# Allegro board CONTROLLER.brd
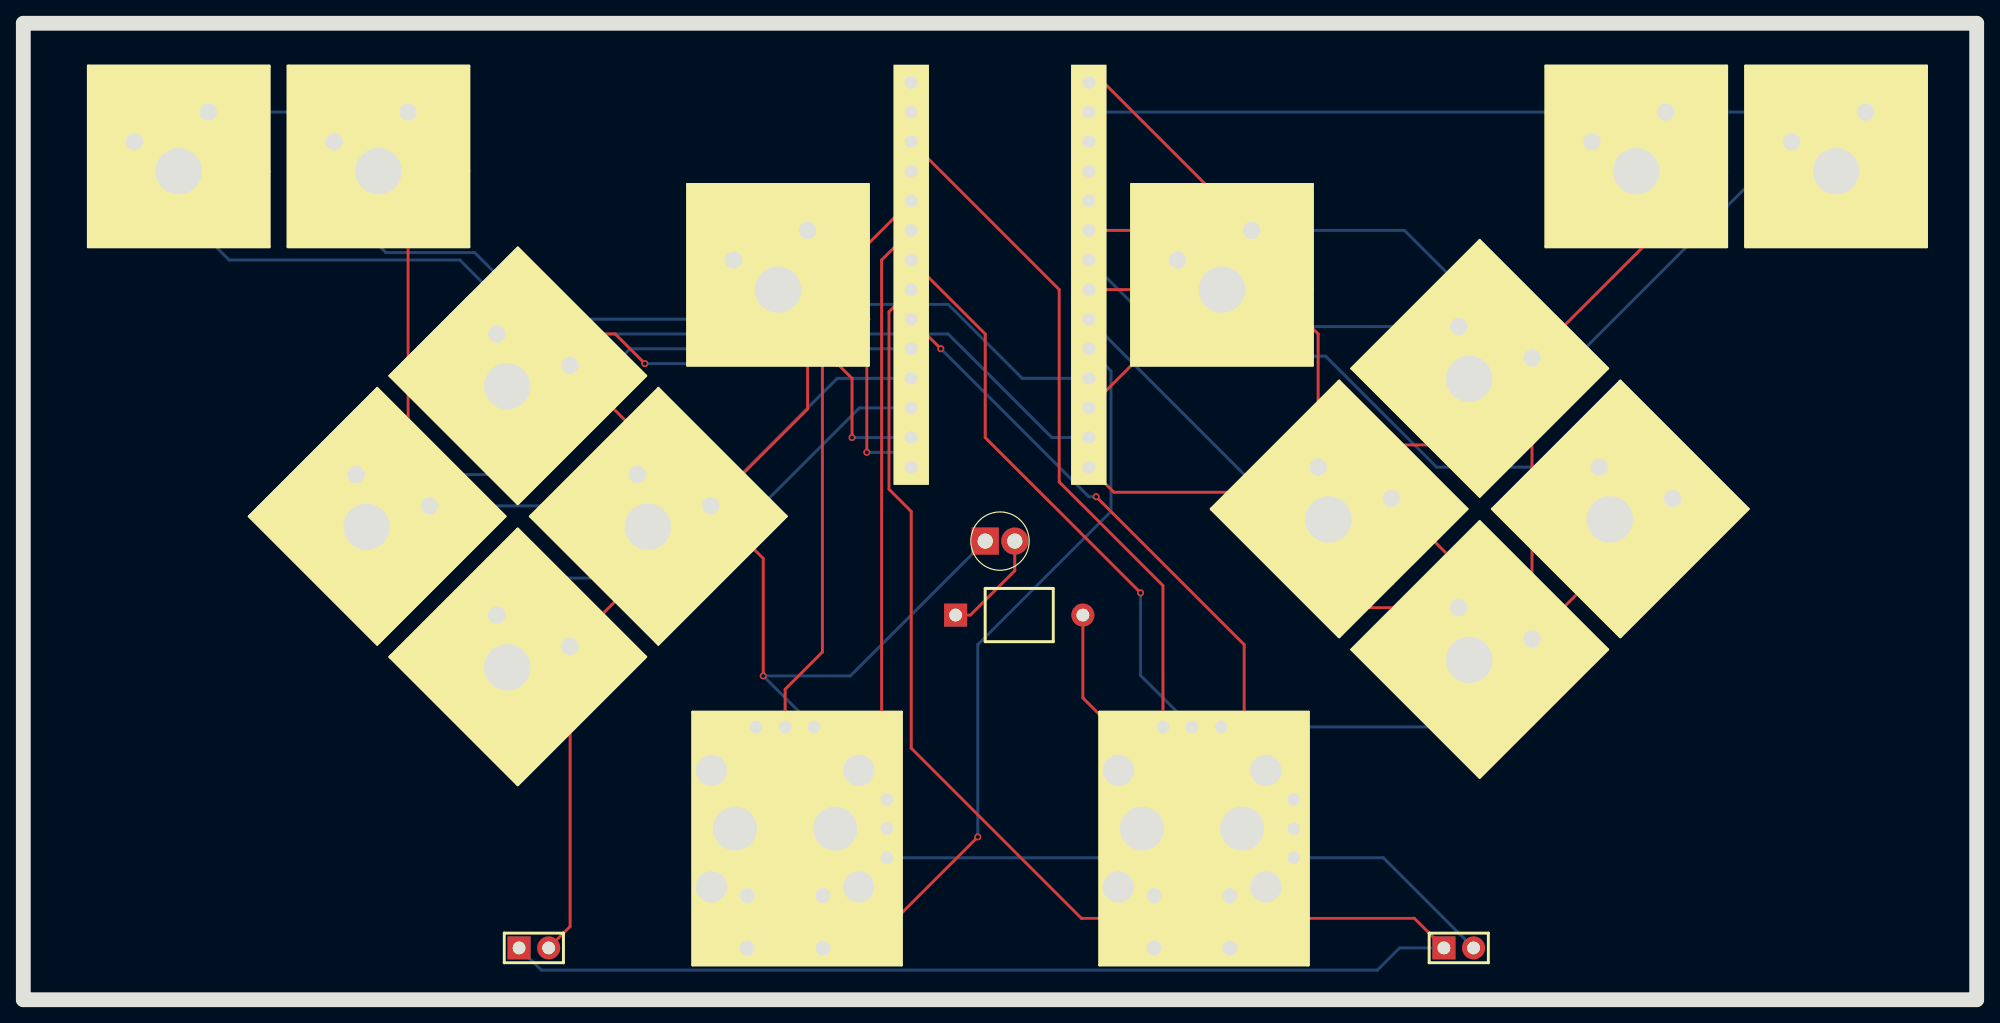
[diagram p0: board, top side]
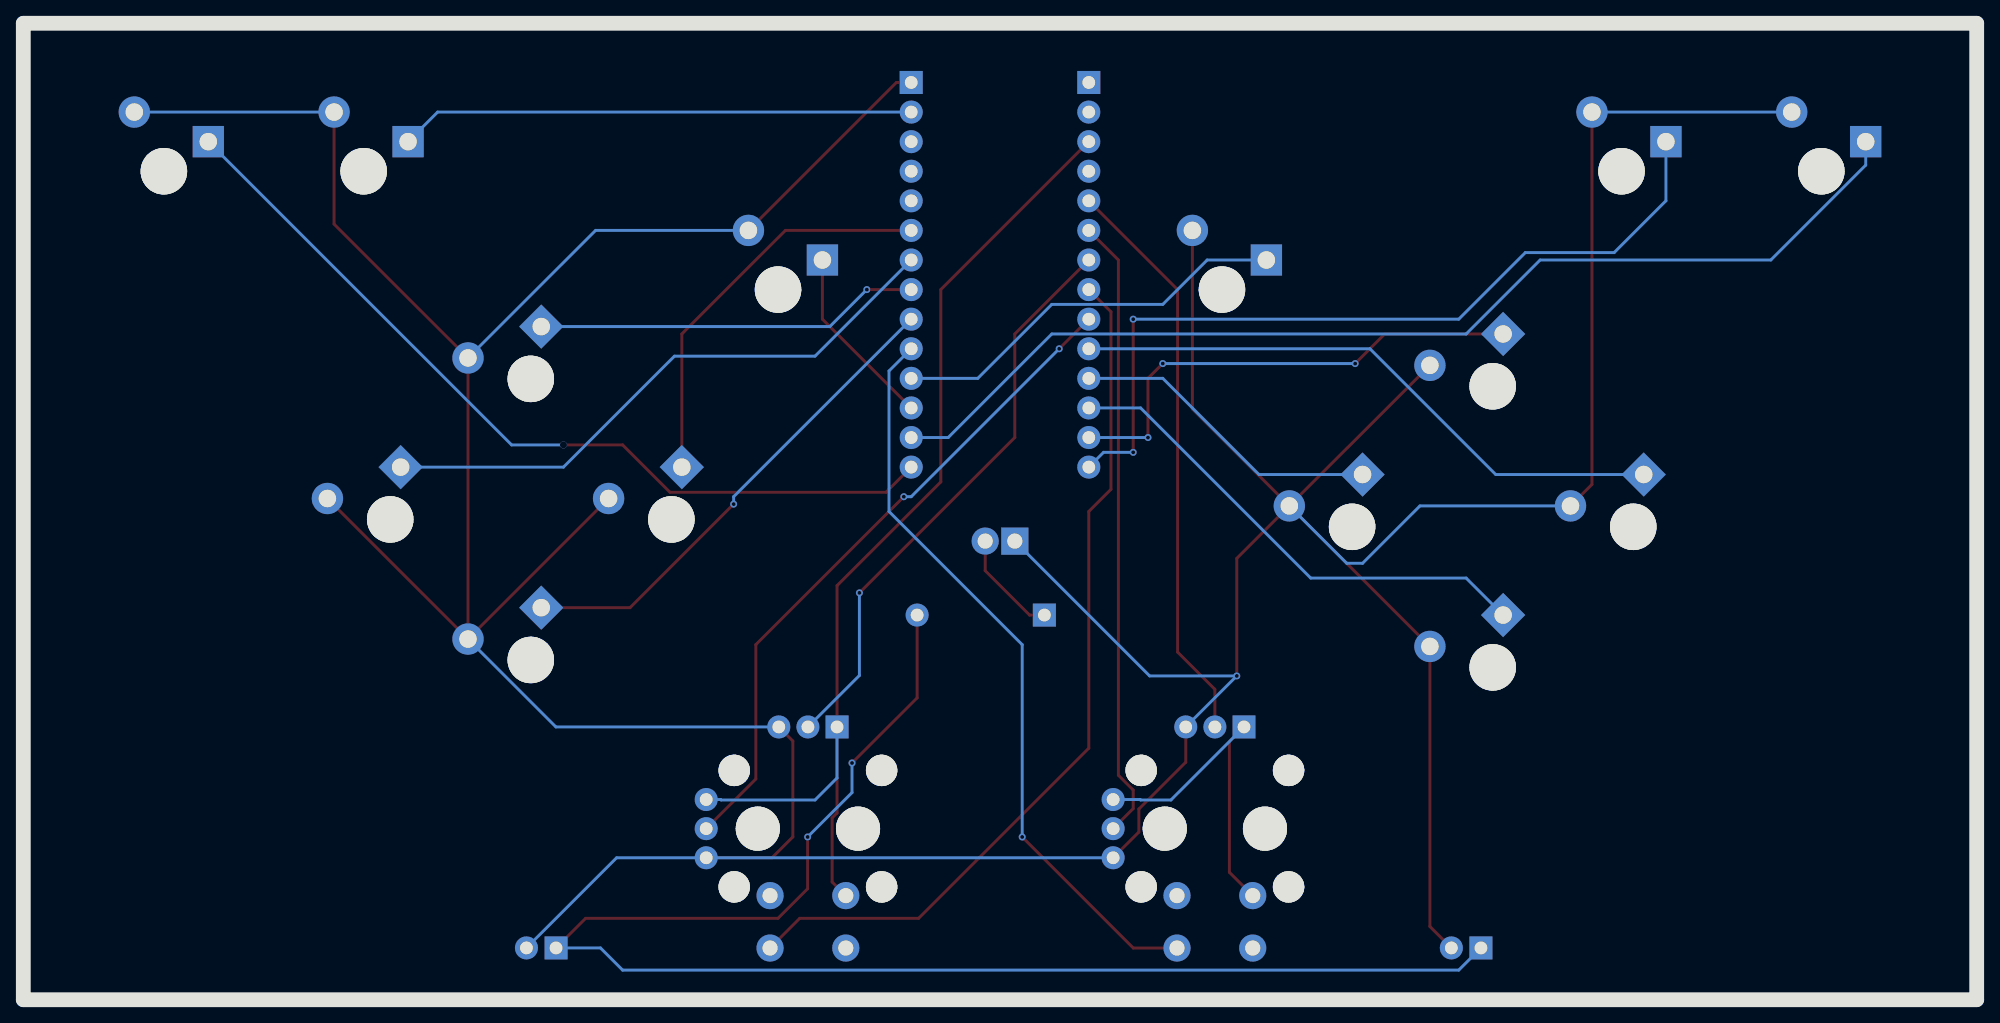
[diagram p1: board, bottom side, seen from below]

Outline 167.64 x 83.82 mm; copper layers: TOP, BOTTOM. Coordinates in mm from the lower left corner of the outline.
Outline path: 0,83.82 0,0 167.64,0 167.64,83.82 0,83.82

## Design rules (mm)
constraint set DEFAULT: min track width 0.127

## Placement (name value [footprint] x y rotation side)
AS1  AnalogStick  [ANALOGSTICK]  93.98 19.68 0 top
AS2  AnalogStick  [ANALOGSTICK]  59.05 19.68 0 top
D1  POWER  [LED]  82.55 39.37 0 top
J1  TeensyRightHeader  [HEADER10]  76.2 78.74 270 top
J2  TeensyLeftHeader  [HEADER10]  91.44 78.74 270 top
MG1  Rumble  [HEADER2]  42.55 4.45 0 top
MG2  Rumble  [HEADER2]  121.92 4.45 0 top
R1  330  [RESISTOR]  80.01 33.02 270 top
SW1  Keyswitch  [KEYSWITCH]  99.06 63.5 0 top
SW2  Keyswitch  [KEYSWITCH]  60.96 63.5 0 top
SW3  Keyswitch  [KEYSWITCH]  123.19 33.66 315 top
SW4  Keyswitch  [KEYSWITCH]  111.12 45.72 315 top
SW5  Keyswitch  [KEYSWITCH]  135.25 45.72 315 top
SW6  Keyswitch  [KEYSWITCH]  123.19 57.78 315 top
SW7  Keyswitch  [KEYSWITCH]  28.57 45.09 315 top
SW8  Keyswitch  [KEYSWITCH]  40.64 57.15 315 top
SW9  Keyswitch  [KEYSWITCH]  40.64 33.02 315 top
SW10  Keyswitch  [KEYSWITCH]  52.7 45.09 315 top
SW11  Keyswitch  [KEYSWITCH]  134.62 73.66 0 top
SW12  Keyswitch  [KEYSWITCH]  151.76 73.66 0 top
SW13  Keyswitch  [KEYSWITCH]  26.67 73.66 0 top
SW14  Keyswitch  [KEYSWITCH]  9.53 73.66 0 top

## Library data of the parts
AS1 AS2 = AnalogStick
D1 = LED
J1 = TeensyRightHeader
J2 = TeensyLeftHeader
MG1 MG2 = Rumble
R1 = Resistor
SW1-SW14 = Keyswitch

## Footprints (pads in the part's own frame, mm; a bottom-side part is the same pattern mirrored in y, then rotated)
ANALOGSTICK
  round 2.692 hole 2.692: (0,0) (0,-10) (12.65,0) (12.65,-10)
  round 3.785 hole 3.785: (2.025,-5) (10.625,-5)
  rect 1.981x1.981 hole 1.092: 1(3.825,3.73)
  round 1.981 hole 1.092: 2(6.325,3.73) 3(8.825,3.73) 4(15.055,-2.5) 5(15.055,-5) 6(15.055,-7.5)
  round 2.337 hole 1.295: 7(3.075,-10.75) 8(3.075,-15.25) 9(9.575,-15.25) 10(9.575,-10.75)
HEADER2
  rect 1.981x1.981 hole 1.092: 1(0,0)
  round 1.981 hole 1.092: 2(2.54,0)
HEADER10
  rect 1.981x1.981 hole 1.092: 1(0,0)
  round 1.981 hole 1.092: 2(2.54,0) 3(5.08,0) 4(7.62,0) 5(10.16,0) 6(12.7,0) 7(15.24,0) 8(17.78,0) 9(20.32,0) 10(22.86,0) 11(25.4,0) 12(27.94,0) 13(30.48,0) 14(33.02,0)
KEYSWITCH
  round 3.988 hole 3.988: (3.81,-2.54)
  rect 2.692x2.692 hole 1.499: 1(0,0)
  round 2.692 hole 1.499: 2(6.35,2.54)
LED
  rect 2.337x2.337 hole 1.295: 1(0,0)
  round 2.337 hole 1.295: 2(2.54,0)
RESISTOR
  rect 1.981x1.981 hole 1.092: 1(0,0)
  round 1.981 hole 1.092: 2(0,10.922)

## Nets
+3.3V: MG1.1 MG2.1 R1.2
GND: AS1.3 AS1.6 AS2.3 AS2.6 D1.1(CATHODE) J2.1(GND) MG1.2(OUT) MG2.2(OUT) SW1.2 SW2.2 SW3.2 SW4.2 SW5.2 SW6.2 SW7.2 SW8.2 SW9.2 SW10.2 SW11.2 SW12.2 SW13.2 SW14.2
+3.3: AS1.1 AS1.4 AS1.7 J1.3
A: J2.9 SW3.1
B: J2.7 SW5.1
D-PAD DOWN: J1.12 SW9.1
D-PAD LEFT: J1.10 SW7.1
D-PAD RIGHT: J1.11 SW10.1
D-PAD UP: J1.13 SW8.1
L1: J1.14 SW13.1
L2: J2.13 SW14.1
R1: J2.2 SW11.1
R2: J2.14 SW12.1
SELECT: J2.11 SW2.1
START: J2.12 SW1.1
X: J2.6 SW4.1
Y: J2.8 SW6.1
N24817: D1.2 R1.1
N49615: AS2.2 J1.5
N49627: AS1.2 J1.7
N49814: AS2.1 AS2.4 AS2.7
N50813: AS2.5 J1.6
N50846: AS1.5 J1.9
N50861: AS1.9 J1.8
N50873: AS2.9 J2.10

Pads without a net: AS1 8 10; AS2 8 10; J1 1 2 4; J2 3 4 5

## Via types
v1: diameter 0.61, hole 0.33, TOP to BOTTOM, 14 vias
v2: diameter 0.61, hole 0.711, TOP to BOTTOM, 1 via

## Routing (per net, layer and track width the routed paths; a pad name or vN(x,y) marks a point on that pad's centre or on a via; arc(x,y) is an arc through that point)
+3.3V: length 132
  TOP w0.254: MG2.1 119.38,6.99 102.87,6.99 100.33,9.53 v1(100.33,13.97) ; R1.2 90.93,25.91 v1(96.52,20.32)
  BOTTOM w0.254: v1(100.33,13.97) 96.52,17.78 v1(96.52,20.32) ; MG2.1 118.11,4.45 116.2,2.54 44.45,2.54 MG1.1
GND: length 478.7
  TOP w0.254: SW7.2 33.02,44.23 SW13.2 ; AS1.6 103.39,12.18 101.6,13.97 101.6,22.21 AS1.3 ; SW2.2 67.31,50.71 SW10.2 ; SW3.2 SW5.2 ; SW3.2 SW4.2 ; SW3.2 SW6.2 140.97,66.58 SW11.2 ; v1(63.5,27.79) 63.5,37.88 SW10.2 ; J2.1 92.71,78.74 SW1.2 ; SW10.2 SW8.2 ; SW10.2 SW9.2 46.93,6.29 MG1.2 ; AS2.6 71.9,14.39 71.9,16.36 67.88,20.39 AS2.3
  BOTTOM w0.254: SW7.2 47.78,42.39 52.7,37.47 54.07,37.47 SW10.2 ; MG2.2 116.72,12.18 AS1.6 AS2.6 ; AS2.3 v1(63.5,27.79) 70.97,27.79 D1.1 ; AS1.3 121.93,23.41 SW3.2 ; SW6.2 118.53,66.04 SW1.2 ; 158.12,76.2 SW11.2 ; SW14.2 SW13.2
+3.3: length 90.7
  TOP w0.254: AS1.7 98.23,10.11 98.23,15.61 97.8,16.03 AS1.1 97.8,35.55 88.9,44.45 88.9,60.96 J1.3
  BOTTOM w0.254: AS1.4 107.79,17.18 107.75,17.14 99.69,17.14 97.8,19.04 AS1.1
A: length 42.4
  TOP w0.254: SW3.1 115.57,33.66 v1(106.68,42.55)
  BOTTOM w0.254: v1(106.68,42.55) 106.68,43.18 J2.9
B: length 51.2
  BOTTOM w0.254: J2.7 99.69,55.24 111.76,55.24 121.28,45.72 SW5.1
D-PAD DOWN: length 42.9
  BOTTOM w0.254: SW9.1 43.81,36.2 57.15,36.2 71.75,50.8 J1.12
D-PAD LEFT: length 52.1
  BOTTOM w0.254: SW7.1 41.27,45.09 52.07,55.88 J1.10
D-PAD RIGHT: length 26.9
  BOTTOM w0.254: SW10.1 61.59,45.09 69.85,53.34 J1.11
D-PAD UP: length 42.2
  TOP w0.254: v1(53.34,54.61) 50.8,57.15 SW8.1 ; v1(71.12,48.26) 71.12,53.34 v1(69.85,54.61)
  BOTTOM w0.254: v1(69.85,54.61) v1(53.34,54.61) ; J1.13 v1(71.12,48.26)
L1: length 70.8
  TOP w0.254: v1(72.39,58.42) v1(72.39,46.99)
  BOTTOM w0.254: v1(72.39,46.99) 74.93,46.99 J1.14 ; v1(72.39,58.42) 44.45,58.42 38.73,64.14 31.11,64.14 26.67,68.58 SW13.1
L2: length 93.6
  BOTTOM w0.254: SW14.1 9.53,71.64 17.67,63.5 37.47,63.5 43.81,57.15 79.38,57.15 88.27,48.26 J2.13
R1: length 44.2
  BOTTOM w0.254: SW11.1 132.08,76.2 J2.2
R2: length 73.7
  TOP w0.254: v2(121.28,47.62) 116.2,47.62 112.14,43.56 93.6,43.56 J2.14
  BOTTOM w0.254: v2(121.28,47.62) 125.73,47.62 SW12.1
SELECT: length 34.7
  BOTTOM w0.254: J2.11 85.72,53.34 79.38,59.69 69.85,59.69 66.04,63.5 SW2.1
START: length 15.9
  TOP w0.254: SW1.1 99.06,58.42 J2.12
X: length 34.8
  TOP w0.254: SW4.1 111.12,57.15 102.23,66.04 J2.6
Y: length 33.1
  TOP w0.254: v1(95.25,60.96) J2.8
  BOTTOM w0.254: v1(95.25,60.96) 98.42,57.78 SW6.1
N24817: length 9.2
  TOP w0.254: R1.1 81.28,33.02 85.09,36.83 D1.2
N49615: length 49.6
  TOP w0.254: J1.5 68.58,60.96 68.58,29.84 65.38,26.65 AS2.2
N49627: length 50.1
  TOP w0.254: J1.7 82.55,57.15 82.55,48.26 v1(95.89,34.92)
  BOTTOM w0.254: AS1.2 95.89,27.84 v1(95.89,34.92)
N49814: length 29.7
  TOP w0.254: AS2.7 64.14,10.94 64.14,22.16 AS2.1
  BOTTOM w0.254: AS2.4 71.79,17.18 71.75,17.14 69.15,17.14 AS2.1
N50813: length 53.6
  TOP w0.254: AS2.5 72.39,16.41 72.39,18 73.66,19.27 73.66,63.5 J1.6
N50846: length 57.7
  TOP w0.254: v1(92.08,43.18) 104.78,30.48 104.78,18.95 AS1.5 ; v1(78.74,55.88) J1.9
  BOTTOM w0.254: v1(78.74,55.88) 91.44,43.18 v1(92.08,43.18)
N50861: length 75.4
  TOP w0.254: J1.8 74.3,59.05 74.3,43.81 76.2,41.91 76.2,21.59 90.81,6.99 101.01,6.99 AS1.9
N50873: length 64.7
  TOP w0.254: AS2.9 72.38,4.44 v1(81.92,13.97)
  BOTTOM w0.254: v1(81.92,13.97) 81.92,30.48 93.34,41.91 93.34,53.98 J2.10
